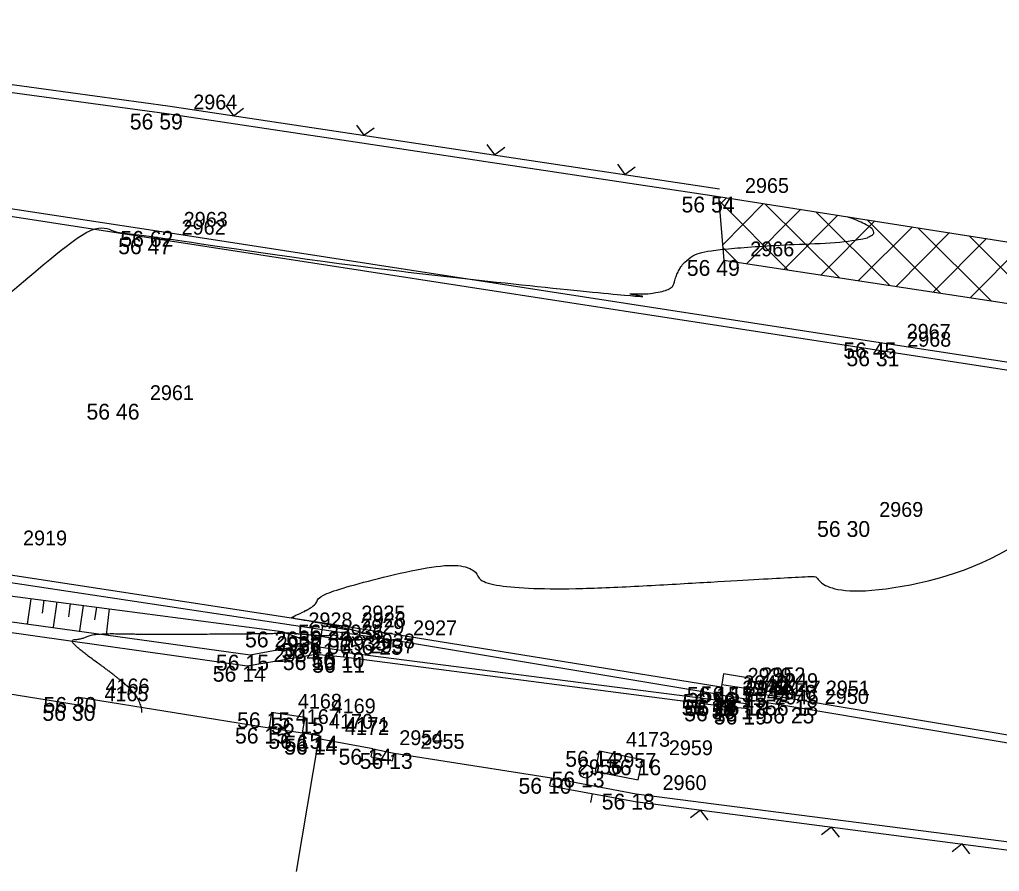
# Model space of a CAD drawing. Extents: x -704017 to -701500, y -1008977 to -1008450.
# Drawn here: x -702444.32 to -702425.78, y -1008783.82 to -1008767.7 of the extents above; entities that cross this region are included whole.
import ezdxf

# ---------------------------------------------------------------- set-up
doc = ezdxf.new("R2010")
doc.units = 0
for name, color, linetype in [('Z_body', 7, 'Continuous'), ('Z_body_cisla', 7, 'Continuous'), ('Z_body_vysky', 7, 'Continuous'), ('Z_budovy', 7, 'Continuous'), ('Z_chodnik', 7, 'Continuous'), ('Z_komunikace', 7, 'Continuous'), ('Z_obruby', 7, 'Continuous'), ('Z_oploceni', 7, 'Continuous'), ('Z_rozhrani_ploch', 7, 'Continuous'), ('Z_site_znaky_kanalizace', 7, 'Continuous'), ('Z_site_znaky_pilire', 7, 'Continuous'), ('Z_teren_hrany_paty', 7, 'Continuous'), ('Z_vrstevnice_vedlejsi', 7, 'Continuous'), ('Z_vstupy', 7, 'Continuous'), ('Z_zelen_souvisla_srafy', 7, 'Continuous')]:
    doc.layers.add(name, color=color, linetype=linetype)

# ---------------------------------------------------------------- blocks, each defined once
blk = doc.blocks.new('POINT_DISPLAY')
blk.add_line((0, 0), (0, 0))
blk = doc.blocks.new('Z212')
for p, q in [((-0.17, 0.17), (0, 0)), ((0, 0), (0.17, 0.17))]:
    blk.add_line(p, q)
blk = doc.blocks.new('Z210')
blk.add_line((0, 0), (0, 0.17))
blk = doc.blocks.new('Z15')
blk.add_circle((0, 0), 0.125)
blk = doc.blocks.new('Z38')
for p, q in [((0.25, 0.2), (-0.25, 0.2)), ((-0.25, 0.2), (-0.25, -0.2)), ((0.25, -0.2), (0.25, 0.2)), ((-0.25, 0), (0.25, 0)), ((-0.25, -0.2), (0.25, -0.2))]:
    blk.add_line(p, q)

msp = doc.modelspace()

# ---------------------------------------------------------------- linework, layer by layer
at = {"layer": 'Z_budovy'}
for p, q in [((-702447.91, -1008779.91), (-702443.21, -1008780.67)), ((-702443.21, -1008780.67), (-702443.19, -1008780.52)), ((-702443.19, -1008780.52), (-702439.59, -1008781.1)), ((-702439.59, -1008781.1), (-702438.96, -1008781.2)), ((-702438.66, -1008781.31), (-702439.08, -1008783.82)), ((-702438.96, -1008781.2), (-702438.65, -1008781.25)), ((-702438.65, -1008781.25), (-702438.66, -1008781.31))]:
    msp.add_line(p, q, dxfattribs=at)
at = {"layer": 'Z_chodnik'}
for p, q in [((-702450.31, -1008778.47), (-702440.01, -1008779.93)), ((-702440.01, -1008779.93), (-702438.71, -1008779.71)), ((-702438.71, -1008779.71), (-702438.18, -1008779.76)), ((-702438.18, -1008779.76), (-702431.09, -1008780.68))]:
    msp.add_line(p, q, dxfattribs=at)
at = {"layer": 'Z_komunikace'}
for p, q in [((-702454.04, -1008769.95), (-702441.75, -1008771.84)), ((-702441.75, -1008771.84), (-702428.02, -1008773.96)), ((-702428.02, -1008773.96), (-702413.55, -1008776.18)), ((-702449.23, -1008777.48), (-702438.35, -1008779.15)), ((-702438.35, -1008779.15), (-702431.04, -1008780.33)), ((-702431.04, -1008780.33), (-702431.07, -1008780.57)), ((-702431.07, -1008780.57), (-702431.09, -1008780.68)), ((-702431.09, -1008780.68), (-702431.06, -1008780.58)), ((-702431.06, -1008780.58), (-702430.57, -1008780.64)), ((-702430.57, -1008780.64), (-702430.54, -1008780.42)), ((-702430.54, -1008780.42), (-702429.56, -1008780.57)), ((-702429.56, -1008780.57), (-702414.84, -1008783.05))]:
    msp.add_line(p, q, dxfattribs=at)
at = {"layer": 'Z_obruby'}
for p, q in [((-702454.02, -1008769.82), (-702441.71, -1008771.7)), ((-702441.71, -1008771.7), (-702428.03, -1008773.81)), ((-702428.03, -1008773.81), (-702413.55, -1008776.04)), ((-702449.25, -1008777.63), (-702438.34, -1008779.28)), ((-702438.34, -1008779.28), (-702437.37, -1008779.42)), ((-702437.37, -1008779.42), (-702431.12, -1008780.46)), ((-702438.18, -1008779.76), (-702438.17, -1008779.67)), ((-702438.17, -1008779.67), (-702431.14, -1008780.57)), ((-702431.12, -1008780.46), (-702431.14, -1008780.57)), ((-702430.53, -1008780.74), (-702430.49, -1008780.57)), ((-702430.49, -1008780.57), (-702429.58, -1008780.72)), ((-702431.09, -1008780.68), (-702430.53, -1008780.74)), ((-702429.58, -1008780.72), (-702414.87, -1008783.19))]:
    msp.add_line(p, q, dxfattribs=at)
at = {"layer": 'Z_oploceni'}
for p, q in [((-702453.42, -1008767.7), (-702441.51, -1008769.33)), ((-702453.44, -1008767.85), (-702441.53, -1008769.48)), ((-702441.51, -1008769.33), (-702431.07, -1008770.9)), ((-702441.53, -1008769.48), (-702431.09, -1008771.05)), ((-702431.09, -1008771.05), (-702430.99, -1008772.25)), ((-702430.99, -1008772.25), (-702413.66, -1008774.9)), ((-702437.66, -1008781.65), (-702437.63, -1008781.5)), ((-702437.63, -1008781.5), (-702437.23, -1008781.58)), ((-702437.66, -1008781.65), (-702437.26, -1008781.73)), ((-702437.26, -1008781.73), (-702437.23, -1008781.58)), ((-702434.28, -1008782.2), (-702434.25, -1008782.05)), ((-702434.25, -1008782.05), (-702432.65, -1008782.35)), ((-702434.28, -1008782.2), (-702432.67, -1008782.5)), ((-702432.65, -1008782.35), (-702423.06, -1008783.59)), ((-702432.67, -1008782.5), (-702423.09, -1008783.74))]:
    msp.add_line(p, q, dxfattribs=at)
at = {"layer": 'Z_rozhrani_ploch'}
for p, q in [((-702450.29, -1008778.29), (-702439.95, -1008779.72)), ((-702439.95, -1008779.72), (-702438.76, -1008779.5)), ((-702438.76, -1008779.5), (-702438.71, -1008779.71))]:
    msp.add_line(p, q, dxfattribs=at)
at = {"layer": 'Z_site_znaky_pilire'}
for p, q in [((-702439.55, -1008780.81), (-702439.59, -1008781.1)), ((-702438.91, -1008780.91), (-702439.55, -1008780.81)), ((-702438.96, -1008781.2), (-702438.91, -1008780.91)), ((-702433.42, -1008781.93), (-702433.34, -1008781.54)), ((-702433.34, -1008781.54), (-702432.53, -1008781.7)), ((-702432.61, -1008782.09), (-702432.53, -1008781.7)), ((-702433.42, -1008781.93), (-702432.61, -1008782.09))]:
    msp.add_line(p, q, dxfattribs=at)
at = {"layer": 'Z_teren_hrany_paty'}
for p, q in [((-702448.35, -1008778.1), (-702439.35, -1008779.28)), ((-702444.1, -1008778.66), (-702444.17, -1008779.14)), ((-702443.86, -1008778.69), (-702443.89, -1008778.93)), ((-702443.61, -1008778.72), (-702443.68, -1008779.2)), ((-702443.36, -1008778.75), (-702443.39, -1008779)), ((-702443.11, -1008778.79), (-702443.18, -1008779.27)), ((-702442.86, -1008778.82), (-702442.9, -1008779.06)), ((-702442.62, -1008778.85), (-702442.68, -1008779.34)), ((-702439.35, -1008779.28), (-702438.76, -1008779.5))]:
    msp.add_line(p, q, dxfattribs=at)
at = {"layer": 'Z_vrstevnice_vedlejsi'}
for points in [[(-702450.531, -1008779.61), (-702451.072, -1008779.082), (-702451.212, -1008778.618), (-702452.159, -1008778.211), (-702450.29, -1008778.29), (-702446.95, -1008778.37), (-702446.318, -1008778.366), (-702446.55, -1008778.08), (-702445.159, -1008778.249), (-702446.525, -1008778.01), (-702449.232, -1008777.495), (-702449.395, -1008777.485), (-702449.559, -1008777.432), (-702449.429, -1008777.319), (-702449.422, -1008777.179), (-702443.116, -1008771.63), (-702442.694, -1008771.685), (-702441.742, -1008771.812), (-702432.054, -1008773.189), (-702431.815, -1008772.208), (-702431.01, -1008772.01), (-702427.421, -1008771.861), (-702428.654, -1008771.432)], [(-702442.003, -1008780.813), (-702441.99, -1008780.713), (-702442.196, -1008780.336), (-702443.443, -1008779.443), (-702443.151, -1008779.429), (-702442.904, -1008779.311), (-702441.95, -1008779.334), (-702439.405, -1008779.32), (-702439.311, -1008779.295), (-702438.515, -1008779.372), (-702438.35, -1008779.325), (-702438.272, -1008779.436), (-702437.37, -1008779.42), (-702438.348, -1008779.172), (-702438.956, -1008779.066), (-702439.187, -1008779.022), (-702439.103, -1008778.982), (-702438.698, -1008778.787), (-702438.633, -1008778.541), (-702435.768, -1008777.853), (-702435.55, -1008778.59), (-702429.38, -1008778.237), (-702429.293, -1008778.233), (-702429.213, -1008778.267), (-702428.971, -1008778.598), (-702425.683, -1008778.255), (-702424.894, -1008776.1), (-702414.433, -1008777.498), (-702413.577, -1008777.812), (-702413.05, -1008776.455), (-702411.4, -1008776.51), (-702409.587, -1008776.69), (-702409.25, -1008776.715), (-702408.573, -1008776.743), (-702408.024, -1008776.73), (-702408.588, -1008776.418), (-702409.064, -1008776.062), (-702409.571, -1008776.244), (-702409.121, -1008775.425), (-702408.678, -1008774.724), (-702408.644, -1008774.624), (-702410.827, -1008774.722), (-702413.431, -1008773.817)]]:
    msp.add_open_spline(points, degree=2, dxfattribs=at)
at = {"layer": 'Z_vstupy'}
for p, q in [((-702437.63, -1008781.5), (-702438.66, -1008781.31)), ((-702437.23, -1008781.58), (-702434.25, -1008782.05))]:
    msp.add_line(p, q, dxfattribs=at)
at = {"layer": 'Z_zelen_souvisla_srafy'}
for p, q in [((-702431.09, -1008771.05), (-702408.56, -1008774.58)), ((-702431.08, -1008771.21), (-702430.94, -1008771.07)), ((-702431.08, -1008771.13), (-702429.77, -1008772.44)), ((-702431.01, -1008771.96), (-702430.24, -1008771.18)), ((-702430.56, -1008772.32), (-702429.53, -1008771.29)), ((-702430.21, -1008771.19), (-702428.81, -1008772.58)), ((-702429.85, -1008772.42), (-702428.83, -1008771.4)), ((-702429.25, -1008771.34), (-702427.85, -1008772.73)), ((-702429.15, -1008772.53), (-702428.13, -1008771.51)), ((-702428.28, -1008771.49), (-702426.89, -1008772.88)), ((-702428.44, -1008772.64), (-702427.42, -1008771.62)), ((-702427.32, -1008771.64), (-702425.93, -1008773.02)), ((-702427.73, -1008772.75), (-702426.72, -1008771.73)), ((-702427.03, -1008772.86), (-702426.02, -1008771.84)), ((-702426.35, -1008771.79), (-702424.97, -1008773.17)), ((-702431.01, -1008772.01), (-702430.73, -1008772.29)), ((-702426.32, -1008772.96), (-702425.32, -1008771.95))]:
    msp.add_line(p, q, dxfattribs=at)

# ---------------------------------------------------------------- block references
at = {"layer": 'Z_body'}
for p in [(-702441.53, -1008769.48), (-702431.09, -1008771.05), (-702441.75, -1008771.84), (-702441.71, -1008771.7), (-702430.99, -1008772.25), (-702428.03, -1008773.81), (-702428.02, -1008773.96), (-702442.35, -1008774.97), (-702428.55, -1008777.19), (-702439.35, -1008779.28), (-702438.35, -1008779.15), (-702438.34, -1008779.28), (-702438.37, -1008779.41), (-702437.37, -1008779.42), (-702438.76, -1008779.5), (-702439.95, -1008779.72), (-702438.71, -1008779.71), (-702438.18, -1008779.76), (-702438.17, -1008779.67), (-702440.01, -1008779.93), (-702431.04, -1008780.33), (-702430.78, -1008780.32), (-702443.19, -1008780.52), (-702431.14, -1008780.57), (-702431.12, -1008780.46), (-702431.07, -1008780.57), (-702431.06, -1008780.58), (-702430.54, -1008780.42), (-702430.49, -1008780.57), (-702429.56, -1008780.57), (-702443.21, -1008780.67), (-702431.09, -1008780.68), (-702431.09, -1008780.68), (-702430.57, -1008780.64), (-702430.53, -1008780.74), (-702429.58, -1008780.72), (-702439.55, -1008780.81), (-702438.91, -1008780.91), (-702439.59, -1008781.1), (-702438.96, -1008781.2), (-702438.66, -1008781.31), (-702438.65, -1008781.25), (-702437.63, -1008781.5), (-702437.23, -1008781.58), (-702433.34, -1008781.54), (-702432.53, -1008781.7), (-702434.25, -1008782.05), (-702433.6, -1008781.93), (-702432.65, -1008782.35)]:
    msp.add_blockref('POINT_DISPLAY', p, dxfattribs=at)
at = {"layer": 'Z_oploceni'}
for name, p, rotation in [('Z212', (-702440.27, -1008769.52), -8.600000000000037), ('Z212', (-702437.8, -1008769.89), -8.600000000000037), ('Z212', (-702435.33, -1008770.26), -8.600000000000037), ('Z212', (-702432.86, -1008770.63), -8.600000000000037), ('Z210', (-702433.48, -1008782.35), 169.4), ('Z212', (-702431.43, -1008782.66), 172.6), ('Z212', (-702428.95, -1008782.98), 172.6), ('Z212', (-702426.48, -1008783.3), 172.6)]:
    msp.add_blockref(name, p, dxfattribs=dict(at, rotation=rotation))
at = {"layer": 'Z_site_znaky_kanalizace', "rotation": -9.000000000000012}
for p in [(-702438.37, -1008779.41), (-702430.78, -1008780.32)]:
    msp.add_blockref('Z38', p, dxfattribs=at)
at = {"layer": 'Z_site_znaky_pilire'}
msp.add_blockref('Z15', (-702433.6, -1008781.93), dxfattribs=at)

# ---------------------------------------------------------------- texts
at = {"layer": 'Z_body_cisla'}
for s, p in [('2964', (-702441.03, -1008769.4)), ('2965', (-702430.59, -1008770.98)), ('2962', (-702441.25, -1008771.77)), ('2963', (-702441.21, -1008771.62)), ('2966', (-702430.49, -1008772.18)), ('2967', (-702427.53, -1008773.74)), ('2968', (-702427.52, -1008773.89)), ('2961', (-702441.85, -1008774.9)), ('2969', (-702428.05, -1008777.11)), ('2919', (-702444.25, -1008777.65)), ('2928', (-702438.85, -1008779.2)), ('2925', (-702437.85, -1008779.07)), ('2926', (-702437.84, -1008779.2)), ('2929', (-702437.87, -1008779.33)), ('2927', (-702436.87, -1008779.35)), ('2936', (-702438.26, -1008779.43)), ('2933', (-702439.45, -1008779.65)), ('2935', (-702438.21, -1008779.64)), ('2937', (-702437.68, -1008779.69)), ('2938', (-702437.67, -1008779.6)), ('2934', (-702439.51, -1008779.86)), ('2939', (-702430.54, -1008780.25)), ('2952', (-702430.28, -1008780.24)), ('4166', (-702442.69, -1008780.45)), ('2941', (-702430.64, -1008780.49)), ('2940', (-702430.62, -1008780.39)), ('2942', (-702430.57, -1008780.49)), ('2944', (-702430.56, -1008780.5)), ('2949', (-702430.04, -1008780.35)), ('2947', (-702429.99, -1008780.49)), ('2951', (-702429.06, -1008780.49)), ('4165', (-702442.71, -1008780.6)), ('2943', (-702430.59, -1008780.61)), ('2945', (-702430.59, -1008780.61)), ('2948', (-702430.07, -1008780.57)), ('2946', (-702430.03, -1008780.66)), ('2950', (-702429.08, -1008780.65)), ('4168', (-702439.05, -1008780.74)), ('4169', (-702438.41, -1008780.83)), ('4167', (-702439.09, -1008781.03)), ('4170', (-702438.46, -1008781.12)), ('4172', (-702438.16, -1008781.24)), ('4171', (-702438.15, -1008781.18)), ('2954', (-702437.13, -1008781.43)), ('2955', (-702436.73, -1008781.5)), ('4173', (-702432.84, -1008781.46)), ('2959', (-702432.03, -1008781.62)), ('2956', (-702433.75, -1008781.98)), ('2957', (-702433.1, -1008781.86)), ('2960', (-702432.15, -1008782.28))]:
    msp.add_text(s, height=0.28, dxfattribs=at).set_placement(p)
at = {"layer": 'Z_body_vysky'}
for s, p in [('56 59', (-702442.23, -1008769.78)), ('56 54', (-702431.79, -1008771.35)), ('56 62', (-702442.41, -1008772)), ('56 47', (-702442.45, -1008772.14)), ('56 49', (-702431.69, -1008772.55)), ('56 45', (-702428.73, -1008774.11)), ('56 31', (-702428.67, -1008774.26)), ('56 46', (-702443.05, -1008775.27)), ('56 30', (-702429.225, -1008777.49)), ('56 26', (-702440.05, -1008779.58)), ('56 23', (-702439.05, -1008779.45)), ('56 35', (-702439.04, -1008779.58)), ('56 06', (-702439.045, -1008779.71)), ('56 25', (-702438.07, -1008779.72)), ('56 11', (-702439.36, -1008779.8)), ('56 10', (-702438.795, -1008779.97)), ('56 15', (-702440.6, -1008780.02)), ('56 10', (-702439.335, -1008780.01)), ('56 11', (-702438.78, -1008780.06)), ('56 14', (-702440.66, -1008780.23)), ('56 15', (-702431.69, -1008780.63)), ('56 15', (-702431.43, -1008780.62)), ('56 30', (-702443.865, -1008780.82)), ('56 18', (-702431.79, -1008780.87)), ('56 19', (-702431.77, -1008780.76)), ('56 17', (-702431.72, -1008780.87)), ('56 15', (-702431.71, -1008780.88)), ('56 15', (-702431.19, -1008780.72)), ('56 19', (-702431.14, -1008780.87)), ('56 18', (-702430.21, -1008780.87)), ('56 30', (-702443.885, -1008780.97)), ('56 18', (-702431.74, -1008780.98)), ('56 18', (-702431.74, -1008780.98)), ('56 17', (-702431.22, -1008780.94)), ('56 19', (-702431.18, -1008781.04)), ('56 25', (-702430.28, -1008781.02)), ('56 15', (-702440.2, -1008781.11)), ('56 15', (-702439.56, -1008781.21)), ('56 15', (-702440.24, -1008781.4)), ('56 15', (-702439.61, -1008781.5)), ('56 14', (-702439.31, -1008781.61)), ('56 14', (-702439.3, -1008781.55)), ('56 14', (-702438.28, -1008781.8)), ('56 13', (-702437.88, -1008781.88)), ('56 14', (-702433.99, -1008781.84)), ('56 16', (-702433.18, -1008782)), ('56 10', (-702434.875, -1008782.35)), ('56 13', (-702434.25, -1008782.23)), ('56 18', (-702433.3, -1008782.65))]:
    msp.add_text(s, height=0.3, dxfattribs=at).set_placement(p)

doc.saveas('drawing.dxf')
